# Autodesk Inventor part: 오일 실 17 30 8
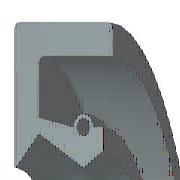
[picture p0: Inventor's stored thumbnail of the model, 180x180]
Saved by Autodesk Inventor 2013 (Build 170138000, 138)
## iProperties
Created: 2012-02
Part Number: 오일 실 17 30 8
Material: 고무
Description: 오일-실
Document SubType Name: Modeling
Standard: KS B 2804
Designer: mduedu
Standards Organization: KS
Language: ko-KR
Size Designation: D - 17 30 8
Categories: <MemberInstance><Categories><Category DisplayName="샤프트 부품" InternalName="7f7aeb1f-a693-4053-b835-cee3144e0d98" Mnemonic="SHFT"><Category DisplayName="실링" Intern
Density: 0.93 g/cm^3
IsCustomPart: 1
Author: mduedu
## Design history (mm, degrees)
revolve "본체" stored, may be unused: angle "d17" = 90 deg
revolve "스프링1" stored, may be unused: angle "d18" = 90 deg
fillet "모깎기3" dims "d43" = 0.5
body "Solid1"
sketch "스케치1"
  geometry: L1 (0, 15)-(8, 15); L2 (8, 13.25)-(1.75, 13.25); L3 (1.75, 10.25)-(4.9, 8.5); L4 (4.9, 8.5)-(0, 8.5); L5 (0, 0)-(9.586, 0) reference; L6 (4.9, 8.5)-(6.3, 9.375); L7 (0, 18)-(0, -3) reference; L8 (-1.941, 0)-(11.507, 0) reference; L9 (4.2, 10.6)-(1.75, 11.21); L10 (1.75, 11.21)-(1.75, 13.25); L11 (0, 15)-(0, 8.588); L12 (4.9, 8.5)-(0, 8.5); L13 (1.75, 10.25)-(0.152, 8.528); L14 (8, 15)-(8, 13.25); L15 (5.6, 10.6)-(6.3, 10.6); L16 (6.3, 10.6)-(6.3, 9.375); C1 r 0.455 at (4.9, 10.6); A1 r 0.7 centre (4.9, 10.6) between (5.6, 10.6) and (4.2, 10.6); A2 r 0.088 centre (0.088, 8.588) between (0, 8.588) and (0.152, 8.528); 1 further point
  constraints: 28 end point, 5 horizontal alignment, 5 point on line, 4 point on circle, 4 vertical alignment, 3 centre point, 3 tangent, 2 collinear, 2 horizontal, 2 perpendicular, 1 coincident, 1 parallel
  dimensions: "d0" = 30 diameter of L1 L5 (= SD2); "d1" = 1.75 distance of L1.end L2.start (= SD); "d2" = 0.91 diameter of C1 (= SPDI); "d3" = 1.4 diameter of A1 (= SPDA); "d4" = 17 diameter of L3.end L5 (= NND); "d5" = 20.5 diameter of L3.start L5 (= TKDM); "d7" = 22.42 diameter of L9.end L5 (= TKDM + 0.24 x SWDT); "d8" = 1.75 distance between parallel lines of L11 L10 (= SD); "d9" = 4.9 distance from line of L11 C1.centre (= SPDST); "d10" = 21.2 diameter of C1.centre L5 (= HLDM); "d11" = 0.0875 radius of A2 (= 0.25 x LAB); "d12" = 6.3 distance between parallel lines of L11 L16 (= SDI); "d13" = 18.75 diameter of L6.end L5 (= ABDM); "d14" = 8 distance from line of L11 L1.end (= SWDT)
fillet "모깎기1" dims "d6" = 0.3 (= RR)
other parameters: "SD2" = 30 [user parameter; used in 1 equation term], "SWDT" = 8 [user parameter; used in 2 equation terms], "RR" = 0.3 [user parameter; used in 1 equation term], "SD" = 1.75 [user parameter; used in 2 equation terms], "NND" = 17 [user parameter; used in 1 equation term], "SPDA" = 1.4 [user parameter; used in 1 equation term], "SPDI" = 0.91 [user parameter; used in 1 equation term], "TKDM" = 20.5 [user parameter; used in 2 equation terms], "HLDM" = 21.2 [user parameter; used in 1 equation term], "ABDM" = 18.75 [user parameter; used in 1 equation term], "SDI" = 6.3 [user parameter; used in 1 equation term], "SPDST" = 4.9 [user parameter; used in 1 equation term], "LAB" = 0.35 [user parameter; used in 1 equation term], "d15" = 0, "d16" = 0, "d19" = 0
